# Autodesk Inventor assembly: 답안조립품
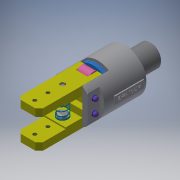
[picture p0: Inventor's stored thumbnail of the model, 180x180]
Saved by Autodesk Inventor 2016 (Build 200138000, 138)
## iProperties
Created: 2019-02
Part Number: 답안조립품
Material: 일반
Document SubType Name: Assembly
Designer: 605-12
Author: 605-12
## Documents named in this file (11)
- C:\Users\605-12\Desktop\490207V1010\490207V1010\답안조립품.iam
- C:\Users\605-12\Desktop\490207V1010\490207V1010\본체.ipt
- C:\Users\605-12\Desktop\490207V1010\490207V1010\O-링.ipt
- C:\Users\605-12\Desktop\490207V1010\490207V1010\피스톤.ipt
- C:\Users\605-12\Desktop\490207V1010\490207V1010\부시.ipt
- C:\Users\605-12\Desktop\490207V1010\490207V1010\평행핀 6x28.ipt
- C:\Users\605-12\Desktop\490207V1010\490207V1010\핀.ipt
- C:\Users\605-12\Desktop\490207V1010\490207V1010\핑거.ipt
- C:\Users\605-12\Desktop\490207V1010\490207V1010\E-링.ipt
- C:\Users\605-12\Desktop\490207V1010\490207V1010\가이드핀.ipt
- C:\Users\605-12\Desktop\490207V1010\490207V1010\스프링.ipt
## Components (13 placed, 6 different names)
1. O-링:1
2. O-링:2
3. 피스톤:1
4. 핀:1
5. 핀:2
6. 핑거:1
7. 핑거:2
8. E-링:1
9. E-링:2
10. 가이드핀:1
11. 가이드핀:2
12. E-링:3
13. E-링:4
